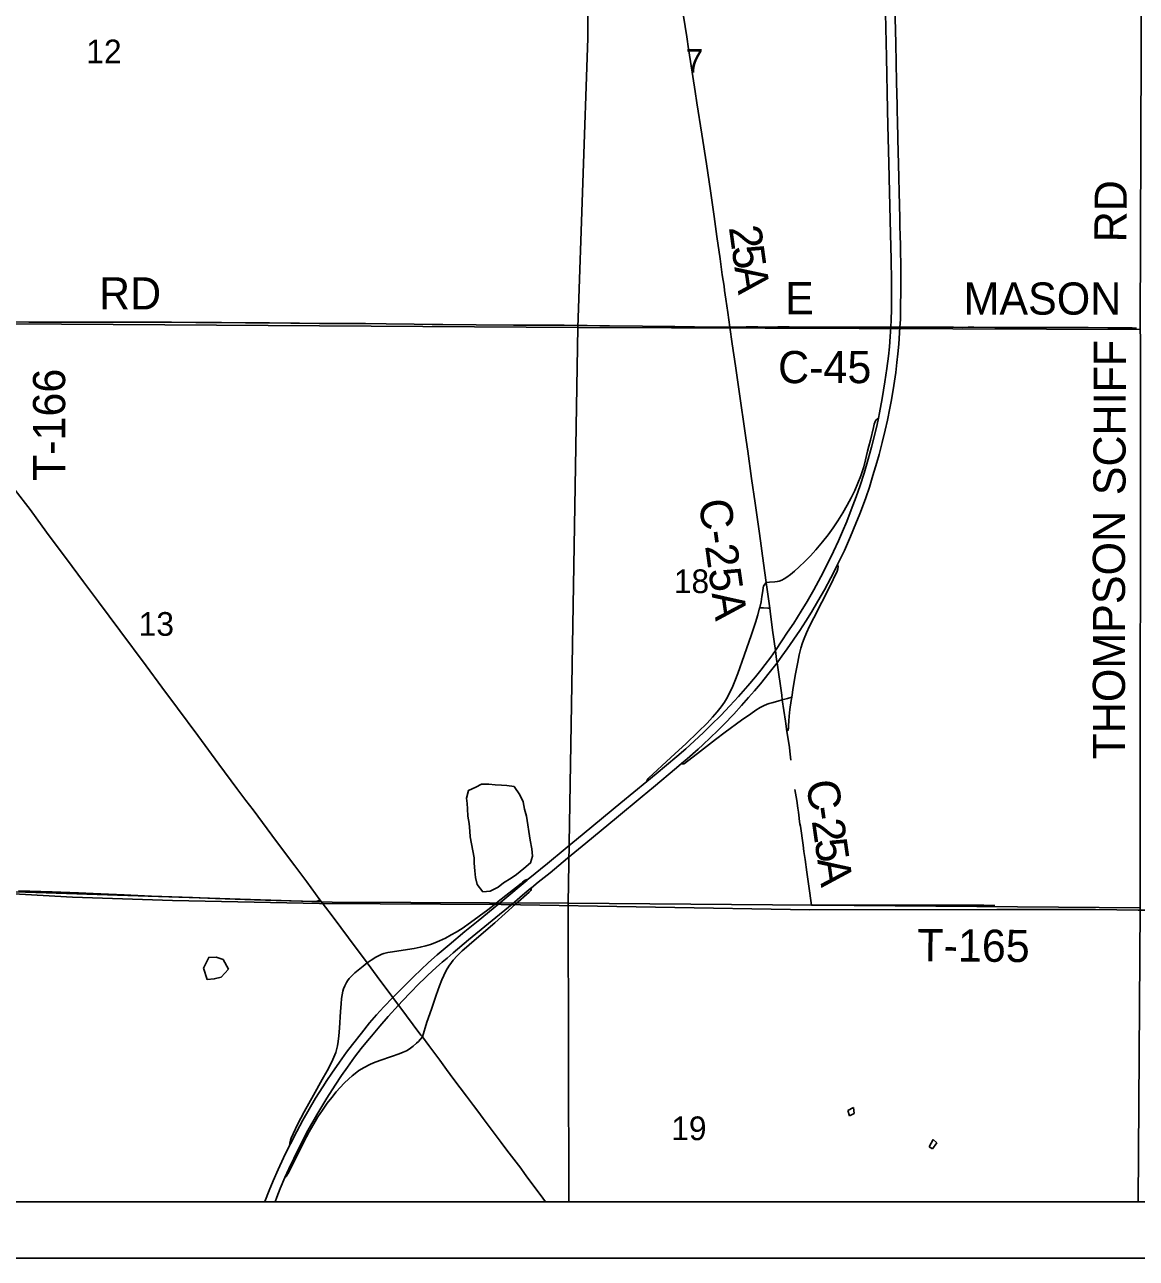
# Model space of a CAD drawing. Extents: x -784 to 1375, y -225 to 440.
# Drawn here: x 480.01 to 519.27, y 281.31 to 324.89 of the extents above; entities that cross this region are included whole.
import ezdxf

# ---------------------------------------------------------------- set-up
doc = ezdxf.new("R2010")
doc.units = 0
for name, color, linetype in [('GM_X_County_Road', 7, 'Continuous'), ('GM_X_County_Road_Text', 7, 'Continuous'), ('GM_X_Interchange_Ramps', 7, 'Continuous'), ('GM_X_Interstate_Route', 7, 'Continuous'), ('GM_X_Minor_Lake', 7, 'Continuous'), ('GM_X_Section', 7, 'Continuous'), ('GM_X_Section_Text', 7, 'Continuous'), ('GM_X_State_Route', 7, 'Continuous'), ('GM_X_Township', 7, 'Continuous'), ('GM_X_Township_Road', 7, 'Continuous'), ('GM_X_Township_Road_Text', 7, 'Continuous'), ('SH_Data', 7, 'Continuous')]:
    doc.layers.add(name, color=color, linetype=linetype)

msp = doc.modelspace()

# ---------------------------------------------------------------- linework, layer by layer
at = {"layer": 'GM_X_County_Road'}
for points in [[(504.915, 314.198), (504.84, 314.725), (504.772, 315.192), (504.728, 315.5), (504.708, 315.648), (504.648, 316.053), (504.568, 316.619), (504.457, 317.407), (504.356, 318.108), (504.225, 319.018), (504.084, 319.977), (503.923, 321.021), (503.75, 322.126), (503.685, 322.531), (503.523, 323.587), (503.455, 324.029), (503.389, 324.459), (503.275, 325.183)], [(479.474, 314.385), (480.159, 314.384), (480.806, 314.384), (481.651, 314.381), (483.49, 314.381), (484.273, 314.377), (485.192, 314.376), (486.05, 314.371), (486.957, 314.363), (487.802, 314.358), (488.659, 314.352), (489.404, 314.343), (489.715, 314.339), (490.423, 314.331), (490.97, 314.329), (492.051, 314.326), (492.772, 314.319), (493.766, 314.308), (494.399, 314.302), (494.772, 314.297), (495.953, 314.286), (497.268, 314.278), (497.988, 314.276), (498.175, 314.273), (498.51, 314.272), (499.057, 314.267), (499.516, 314.263), (499.877, 314.261), (500.324, 314.254), (500.659, 314.25), (501.827, 314.237), (502.56, 314.231), (502.97, 314.226), (503.666, 314.213), (504.25, 314.206), (504.498, 314.201), (504.915, 314.198)], [(504.915, 314.198), (505.109, 314.204), (505.184, 314.206), (505.494, 314.212), (505.904, 314.209), (506.326, 314.207), (506.612, 314.209), (507.009, 314.209), (507.704, 314.206), (508.288, 314.206), (508.748, 314.206), (509.22, 314.205), (510.594, 314.2), (510.921, 314.2), (511.755, 314.198), (512.239, 314.198), (512.81, 314.198), (513.121, 314.195), (513.332, 314.198), (513.531, 314.199), (514.276, 314.195), (515.047, 314.194), (515.743, 314.194), (517.569, 314.185), (518.265, 314.182), (518.737, 314.18), (519.122, 314.174), (519.27, 314.165)], [(506.193, 305.184), (506.099, 305.867), (505.957, 306.914), (505.808, 307.985), (505.683, 308.858), (505.546, 309.818), (505.491, 310.212), (505.221, 312.094), (505.113, 312.831), (504.998, 313.618), (504.915, 314.198)], [(506.32, 304.281), (506.216, 305.018), (506.193, 305.184)], [(506.567, 302.458), (506.522, 302.784), (506.424, 303.504), (506.335, 304.169), (506.32, 304.281)], [(506.766, 301.032), (506.746, 301.202), (506.583, 302.348), (506.567, 302.458)], [(506.928, 299.914), (506.876, 300.28), (506.766, 301.032)], [(507.015, 299.35), (506.957, 299.714), (506.928, 299.914)], [(507.07, 298.905), (507.03, 299.222), (507.015, 299.35)], [(507.348, 296.969), (507.334, 297.074), (507.315, 297.209), (507.274, 297.48), (507.214, 297.871)], [(507.532, 295.679), (507.501, 295.905), (507.405, 296.569), (507.391, 296.654), (507.379, 296.74), (507.348, 296.969)], [(507.8, 293.787), (507.704, 294.457), (507.634, 294.948), (507.571, 295.402), (507.532, 295.679)], [(479.793, 294.292), (480.974, 294.251), (481.905, 294.217), (482.426, 294.195), (483.519, 294.146), (484.488, 294.104), (485.941, 294.053), (486.749, 294.024), (488.128, 293.976), (488.886, 293.953), (489.817, 293.921), (490.175, 293.911), (490.243, 293.911), (490.303, 293.917), (490.339, 293.926), (490.378, 293.941), (490.437, 293.975)]]:
    msp.add_lwpolyline(points, dxfattribs=at)
at = {"layer": 'GM_X_Interchange_Ramps'}
for points in [[(510.158, 310.991), (510.112, 310.956), (510.076, 310.924), (510.044, 310.873), (510.015, 310.781), (509.983, 310.653), (509.878, 310.216), (509.827, 310.004), (509.781, 309.827), (509.706, 309.516), (509.641, 309.268), (509.536, 308.953), (509.432, 308.686), (509.323, 308.436), (509.198, 308.179), (509.057, 307.915), (508.902, 307.646), (508.725, 307.36), (508.56, 307.112), (508.386, 306.87), (508.185, 306.616), (507.952, 306.341), (507.761, 306.129), (507.562, 305.924), (507.365, 305.734), (507.199, 305.584), (507.056, 305.464), (506.926, 305.368), (506.831, 305.309), (506.754, 305.27), (506.661, 305.235), (506.589, 305.216), (506.503, 305.202), (506.317, 305.191), (506.193, 305.184)], [(506.928, 299.914), (506.958, 299.952), (506.969, 299.973), (506.975, 299.996), (506.983, 300.042), (506.987, 300.116), (507.001, 300.301), (507.01, 300.462), (507.035, 300.697), (507.079, 301.017), (507.099, 301.133), (507.153, 301.471), (507.237, 301.961), (507.31, 302.365), (507.367, 302.632), (507.426, 302.861), (507.485, 303.051), (507.538, 303.203), (507.617, 303.399), (507.726, 303.636), (507.876, 303.936), (508.163, 304.488), (508.435, 305.019), (508.707, 305.581), (508.729, 305.662), (508.734, 305.738), (508.717, 305.813)], [(506.193, 305.184), (506.144, 305.127), (506.122, 305.091), (506.106, 305.053), (506.094, 304.994), (506.074, 304.891), (506.046, 304.682), (506.014, 304.499), (505.971, 304.305), (505.965, 304.283), (505.899, 304.041), (505.815, 303.768), (505.673, 303.344), (505.417, 302.605), (505.194, 301.972), (505.088, 301.694), (504.991, 301.465), (504.895, 301.263), (504.825, 301.131), (504.724, 300.96), (504.606, 300.785), (504.469, 300.609), (504.306, 300.421), (504.109, 300.215), (503.8, 299.908), (503.359, 299.489), (503.112, 299.262), (502.825, 299.006), (502.042, 298.273), (502.018, 298.246), (502.004, 298.223), (501.993, 298.196), (501.986, 298.175), (501.983, 298.148)], [(506.32, 304.281), (506.252, 304.281), (506.104, 304.283), (505.99, 304.283), (505.965, 304.283)], [(506.766, 301.032), (506.951, 301.09), (507.099, 301.133)], [(503.207, 298.784), (503.208, 298.783), (503.238, 298.776), (503.266, 298.777), (503.29, 298.782), (503.311, 298.794), (503.875, 299.227), (504.406, 299.638), (504.745, 299.891), (505.329, 300.314), (505.652, 300.545), (505.837, 300.671), (505.985, 300.763), (506.105, 300.828), (506.23, 300.884), (506.3, 300.908), (506.396, 300.935), (506.604, 300.989), (506.766, 301.032)], [(497.791, 294.697), (497.758, 294.693), (497.723, 294.683), (497.683, 294.662), (497.633, 294.626), (497.589, 294.591), (497.538, 294.551), (496.731, 293.914), (496.633, 293.836), (496.362, 293.62), (496.065, 293.394), (495.753, 293.169), (495.456, 292.965), (495.246, 292.832), (495.075, 292.732), (494.866, 292.621), (494.664, 292.526), (494.492, 292.455), (494.34, 292.4), (494.174, 292.348), (493.981, 292.299), (493.762, 292.254), (493.529, 292.216), (493.001, 292.14), (492.83, 292.107), (492.697, 292.074), (492.627, 292.05), (492.525, 292.005), (492.415, 291.946), (492.248, 291.839), (492.105, 291.752)], [(494.056, 289.129), (494.212, 289.646), (494.372, 290.116), (494.542, 290.609), (494.656, 290.938), (494.737, 291.146), (494.807, 291.305), (494.891, 291.471), (494.988, 291.631), (495.081, 291.762), (495.143, 291.84), (495.284, 291.997), (495.463, 292.169), (495.612, 292.3), (495.799, 292.464), (496.609, 293.16), (497.344, 293.814), (497.822, 294.24), (497.85, 294.266), (497.869, 294.288), (497.882, 294.308), (497.895, 294.339), (497.907, 294.394)], [(492.105, 291.752), (491.958, 291.629), (491.671, 291.39), (491.562, 291.29), (491.469, 291.19), (491.409, 291.11), (491.369, 291.047), (491.312, 290.937), (491.272, 290.833), (491.247, 290.75), (491.219, 290.616), (491.199, 290.482), (491.181, 290.296), (491.165, 290.023), (491.132, 289.44), (491.108, 289.168), (491.081, 288.971), (491.052, 288.812), (490.993, 288.584), (490.896, 288.329), (490.785, 288.107), (490.692, 287.932), (490.52, 287.628), (490.209, 287.077), (489.878, 286.48), (489.644, 286.041), (489.424, 285.558), (489.398, 285.477), (489.387, 285.43), (489.379, 285.382), (489.375, 285.353), (489.366, 285.296)], [(489.202, 284.168), (489.229, 284.185), (489.251, 284.209), (489.272, 284.241), (489.303, 284.288), (489.665, 285.014), (489.873, 285.424), (490.06, 285.776), (490.219, 286.057), (490.367, 286.302), (490.523, 286.542), (490.694, 286.786), (490.852, 286.995), (491.009, 287.188), (491.148, 287.346), (491.293, 287.5), (491.455, 287.655), (491.577, 287.761), (491.734, 287.883), (491.816, 287.939), (491.996, 288.05), (492.196, 288.151), (492.332, 288.211), (492.552, 288.297), (492.963, 288.44), (493.234, 288.534), (493.373, 288.587), (493.497, 288.644), (493.551, 288.675), (493.634, 288.729), (493.733, 288.805), (493.845, 288.904), (493.917, 288.973), (494.056, 289.129)]]:
    msp.add_lwpolyline(points, dxfattribs=at)
at = {"layer": 'GM_X_Interstate_Route'}
for points in [[(488.85, 283.309), (488.911, 283.466), (489.037, 283.777), (489.202, 284.168), (489.338, 284.474), (489.675, 285.173), (489.78, 285.387), (489.852, 285.522), (489.941, 285.69), (490.013, 285.824), (490.33, 286.372), (490.682, 286.972), (490.97, 287.423), (491.198, 287.764), (491.405, 288.059), (491.661, 288.411), (491.895, 288.717), (492.112, 288.989), (492.255, 289.162), (492.55, 289.514), (492.844, 289.853), (493.212, 290.254), (493.358, 290.41), (493.631, 290.699), (493.935, 291.009), (494.14, 291.21), (494.239, 291.304), (494.559, 291.598), (494.755, 291.771), (494.924, 291.917), (495.142, 292.103), (495.685, 292.557), (497.227, 293.825), (497.678, 294.204), (497.888, 294.379), (497.907, 294.394), (498.148, 294.591), (498.562, 294.929), (499.182, 295.447), (499.823, 295.979), (500.91, 296.869), (501.819, 297.622), (502.22, 297.956), (503.031, 298.633), (503.207, 298.784), (503.409, 298.956), (503.791, 299.292), (503.957, 299.442), (504.236, 299.706), (504.476, 299.941), (504.704, 300.169), (505.05, 300.526), (505.322, 300.832), (505.578, 301.12), (505.783, 301.353), (505.994, 301.608), (506.302, 301.986), (506.583, 302.348), (506.75, 302.577), (506.936, 302.842), (507.383, 303.487), (507.601, 303.819), (507.798, 304.135), (508.026, 304.52), (508.252, 304.92), (508.48, 305.347), (508.689, 305.756), (508.717, 305.813), (508.826, 306.035), (508.957, 306.316), (509.173, 306.804), (509.366, 307.262), (509.505, 307.608), (509.597, 307.851), (509.714, 308.179), (509.841, 308.555), (509.868, 308.638), (509.969, 308.957), (510.063, 309.266), (510.108, 309.421), (510.188, 309.708), (510.297, 310.129), (510.402, 310.564), (510.48, 310.915), (510.566, 311.341), (510.62, 311.634), (510.703, 312.136), (510.772, 312.603), (510.816, 312.948), (510.849, 313.257), (510.879, 313.603), (510.921, 314.2), (510.935, 314.47), (510.945, 314.867), (510.953, 315.551), (510.951, 316.222), (510.936, 317.079), (510.929, 317.464), (510.922, 317.749), (510.914, 318.06), (510.904, 318.495), (510.867, 319.961), (510.845, 320.843), (510.829, 321.514), (510.823, 321.8), (510.818, 322.048), (510.801, 322.856), (510.785, 323.539), (510.77, 324.222), (510.727, 326.049)], [(488.491, 283.309), (488.491, 283.311), (488.643, 283.705), (488.785, 284.049), (488.96, 284.447), (489.155, 284.863), (489.366, 285.296), (489.395, 285.354), (489.615, 285.786), (489.833, 286.19), (490.053, 286.579), (490.283, 286.962), (490.533, 287.362), (490.682, 287.591), (490.855, 287.849), (491.125, 288.236), (491.38, 288.588), (491.589, 288.866), (491.902, 289.267), (492.192, 289.624), (492.434, 289.907), (492.691, 290.193), (493.011, 290.524), (493.142, 290.655), (493.289, 290.806), (493.749, 291.26), (494, 291.501), (494.274, 291.753), (494.58, 292.025), (495.005, 292.387), (495.558, 292.85), (496.019, 293.228), (496.749, 293.83), (496.892, 293.947), (497.76, 294.672), (497.791, 294.697), (498.469, 295.258), (499.103, 295.778), (499.766, 296.322), (501.069, 297.397), (501.983, 298.148), (502.317, 298.423), (503.041, 299.031), (503.36, 299.308), (503.656, 299.574), (503.982, 299.88), (504.258, 300.149), (504.59, 300.485), (504.915, 300.828), (505.217, 301.158), (505.544, 301.532), (505.818, 301.855), (506.006, 302.086), (506.162, 302.28), (506.362, 302.55), (506.522, 302.784), (506.745, 303.116), (506.955, 303.424), (507.168, 303.745), (507.433, 304.166), (507.639, 304.507), (507.88, 304.928), (508.122, 305.377), (508.372, 305.863), (508.575, 306.276), (508.748, 306.649), (508.893, 306.979), (509.041, 307.335), (509.204, 307.752), (509.372, 308.207), (509.511, 308.607), (509.653, 309.044), (509.804, 309.545), (509.919, 309.964), (510.022, 310.374), (510.111, 310.763), (510.158, 310.991), (510.196, 311.177), (510.289, 311.678), (510.388, 312.267), (510.459, 312.747), (510.514, 313.179), (510.547, 313.513), (510.576, 313.872), (510.594, 314.2), (510.606, 314.456), (510.62, 314.829), (510.627, 315.252), (510.625, 315.836), (510.61, 316.594), (510.585, 317.501), (510.552, 318.967), (510.527, 319.999), (510.498, 321.328), (510.483, 321.875), (510.447, 323.738), (510.394, 325.826)]]:
    msp.add_lwpolyline(points, dxfattribs=at)
at = {"layer": 'GM_X_Minor_Lake'}
for p, q in [((497.856, 296.078), (497.729, 296.925)), ((495.741, 296.193), (495.88, 295.455)), ((509.086, 286.535), (509.142, 286.348)), ((509.142, 286.348), (509.305, 286.424)), ((509.305, 286.424), (509.285, 286.637)), ((512.227, 285.383), (512.094, 285.501)), ((511.957, 285.249), (512.068, 285.179)), ((512.068, 285.179), (512.227, 285.383))]:
    msp.add_line(p, q, dxfattribs=at)
for points in [[(497.729, 296.925), (497.665, 297.177), (497.609, 297.436), (497.499, 297.681), (497.291, 297.973), (497.033, 298.016), (496.843, 298.02), (496.631, 298.04), (496.396, 298.06), (496.137, 298.057), (495.945, 297.955), (495.685, 297.839), (495.612, 297.568), (495.639, 297.378), (495.643, 297.188), (495.662, 296.93), (495.703, 296.664), (495.729, 296.398), (495.741, 296.193)], [(495.88, 295.455), (495.884, 295.265), (495.903, 294.999), (495.929, 294.756), (495.993, 294.52), (496.194, 294.25), (496.453, 294.283), (496.729, 294.421), (496.922, 294.569), (497.19, 294.738), (497.383, 294.87), (497.637, 295.077), (497.869, 295.277), (497.949, 295.518), (497.915, 295.769), (497.856, 296.078)], [(487.206, 291.526), (487.017, 291.862), (486.767, 291.951), (486.509, 291.941), (486.323, 291.564)], [(486.323, 291.564), (486.45, 291.161), (486.701, 291.179), (486.953, 291.242), (487.206, 291.526)], [(509.285, 286.637), (509.086, 286.535)], [(512.094, 285.501), (511.957, 285.249)]]:
    msp.add_lwpolyline(points, dxfattribs=at)
at = {"layer": 'GM_X_Section'}
for p, q in [((479.22, 283.309), (499.224, 283.309)), ((499.224, 283.309), (519.336, 283.309))]:
    msp.add_line(p, q, dxfattribs=at)
for points in [[(479.62, 334.419), (499.931, 334.47), (499.901, 324.411), (499.543, 314.191), (479.486, 314.324)], [(519.48, 333.952), (519.411, 314.122), (499.543, 314.191), (499.901, 324.411), (499.931, 334.47)], [(499.543, 314.191), (499.2, 293.85), (490.868, 293.892), (479.323, 294.268), (479.486, 314.324)], [(519.411, 314.122), (519.42, 313.796), (519.407, 293.691), (499.2, 293.85), (499.543, 314.191)]]:
    msp.add_lwpolyline(points, close=True, dxfattribs=at)
for points in [[(499.224, 283.309), (499.2, 293.85), (490.868, 293.892), (479.323, 294.268), (479.22, 283.309)], [(519.336, 283.309), (519.407, 293.691), (499.2, 293.85), (499.224, 283.309)]]:
    msp.add_lwpolyline(points, dxfattribs=at)
at = {"layer": 'GM_X_State_Route'}
for points in [[(479.641, 308.486), (480.034, 307.973), (480.201, 307.756), (480.414, 307.465), (480.78, 306.963), (481.687, 305.748), (482.089, 305.211), (482.614, 304.502), (483.369, 303.483), (484.295, 302.236), (484.85, 301.487), (485.407, 300.74), (486.125, 299.772), (486.87, 298.762), (487.504, 297.902), (487.82, 297.486), (488.074, 297.149), (488.902, 296.029), (489.544, 295.175), (489.97, 294.61), (490.437, 293.975)], [(490.437, 293.975), (490.437, 293.975), (490.831, 293.46), (491.169, 293), (491.718, 292.263), (492.086, 291.778), (492.105, 291.752), (492.462, 291.269), (493.011, 290.524), (493.212, 290.254), (493.219, 290.245)], [(493.219, 290.245), (494.004, 289.197), (494.056, 289.129), (494.286, 288.823)], [(494.286, 288.823), (494.665, 288.307)], [(494.665, 288.307), (494.783, 288.145)], [(494.783, 288.145), (494.902, 287.983), (495.171, 287.626), (495.613, 287.04)], [(495.613, 287.04), (495.859, 286.713), (496.013, 286.503), (496.197, 286.252), (496.56, 285.779), (496.84, 285.399), (497.039, 285.129), (497.532, 284.489), (497.66, 284.307), (497.777, 284.146), (498.218, 283.56), (498.406, 283.309)]]:
    msp.add_lwpolyline(points, dxfattribs=at)
at = {"layer": 'GM_X_Township'}
msp.add_line((458.267, 283.309), (539.084, 283.309), dxfattribs=at)
for points in [[(519.34, 293.604), (517.829, 293.627), (516.502, 293.627), (514.346, 293.626), (507.742, 293.624), (496.837, 293.807), (490.416, 293.843), (485.23, 293.95), (481.696, 294.072), (478.992, 294.22), (476.854, 294.139), (474.329, 294.056), (470.984, 294.092), (462.46, 294.056), (458.296, 294.134), (458.336, 314.323), (458.289, 334.394)], [(539.084, 283.309), (539.15, 292.161), (539.16, 293.586), (533.956, 293.601), (527.265, 293.606), (519.34, 293.604), (517.829, 293.627), (516.502, 293.627), (514.346, 293.626), (507.742, 293.624), (496.837, 293.807), (490.416, 293.843), (485.23, 293.95), (481.696, 294.072), (478.992, 294.22), (476.854, 294.139), (474.329, 294.056), (470.984, 294.092), (462.46, 294.056), (458.296, 294.134), (458.263, 284.231), (458.267, 283.309)]]:
    msp.add_lwpolyline(points, dxfattribs=at)
at = {"layer": 'GM_X_Township_Road'}
for points in [[(507.8, 293.787), (508.394, 293.781), (508.706, 293.783), (508.992, 293.782), (509.303, 293.782), (509.65, 293.78), (509.899, 293.779), (510.26, 293.78), (510.658, 293.779), (511.155, 293.782), (511.541, 293.784)], [(511.541, 293.784), (511.99, 293.787), (512.636, 293.784), (513.144, 293.784), (513.889, 293.779), (514.273, 293.773)]]:
    msp.add_lwpolyline(points, dxfattribs=at)
at = {"layer": 'SH_Data'}
for p, q in [((444.236, 283.309), (580.236, 283.309)), ((442.236, 281.309), (581.184, 281.309))]:
    msp.add_line(p, q, dxfattribs=at)

# ---------------------------------------------------------------- texts
at = {"layer": 'GM_X_County_Road_Text'}
for s, height, rotation, p in [('2', 1.136, 277.888, (504.876, 317.726)), ('5', 1.136, 277.888, (504.972, 317.033)), ('RD', 1.1364, 0, (482.633, 314.828)), ('A', 1.136, 278.5335, (505.07, 316.325)), ('E', 1.136, 0, (506.867, 314.661)), ('MASON', 1.1364, 0, (513.167, 314.645)), ('C-45', 1.1364, 0, (506.617, 312.224)), ('C-25A', 1.1364, 278.0266, (503.811, 308.061)), ('C', 1.136, 278.2675, (507.604, 298.138)), ('-', 1.136, 278.2265, (507.737, 297.221)), ('2', 1.136, 278.1736, (507.803, 296.764)), ('5', 1.136, 278.1316, (507.902, 296.077)), ('A', 1.136, 278.1288, (508, 295.389))]:
    msp.add_text(s, height=height, rotation=rotation, dxfattribs=at).set_placement(p)
at = {"layer": 'GM_X_Section_Text'}
for s, height, p in [('12', 0.8371, (482.186, 323.522)), ('7', 0.837, (503.353, 323.193)), ('18', 0.8371, (502.936, 304.807)), ('13', 0.8371, (484.036, 303.299)), ('19', 0.8371, (502.845, 285.483))]:
    msp.add_text(s, height=height, rotation=0, dxfattribs=at).set_placement(p)
at = {"layer": 'GM_X_Township_Road_Text'}
for s, rotation, p in [('RD', 89.5093, (518.92, 317.195)), ('SCHIFF', 89.7985, (518.886, 308.264)), ('T-166', 90, (481.439, 308.765)), ('THOMPSON', 90, (518.87, 298.931)), ('T-165', 359.4503, (511.53, 291.809))]:
    msp.add_text(s, height=1.1364, rotation=rotation, dxfattribs=at).set_placement(p)

doc.saveas('drawing.dxf')
